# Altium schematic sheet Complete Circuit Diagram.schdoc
size 324 x 171 mm
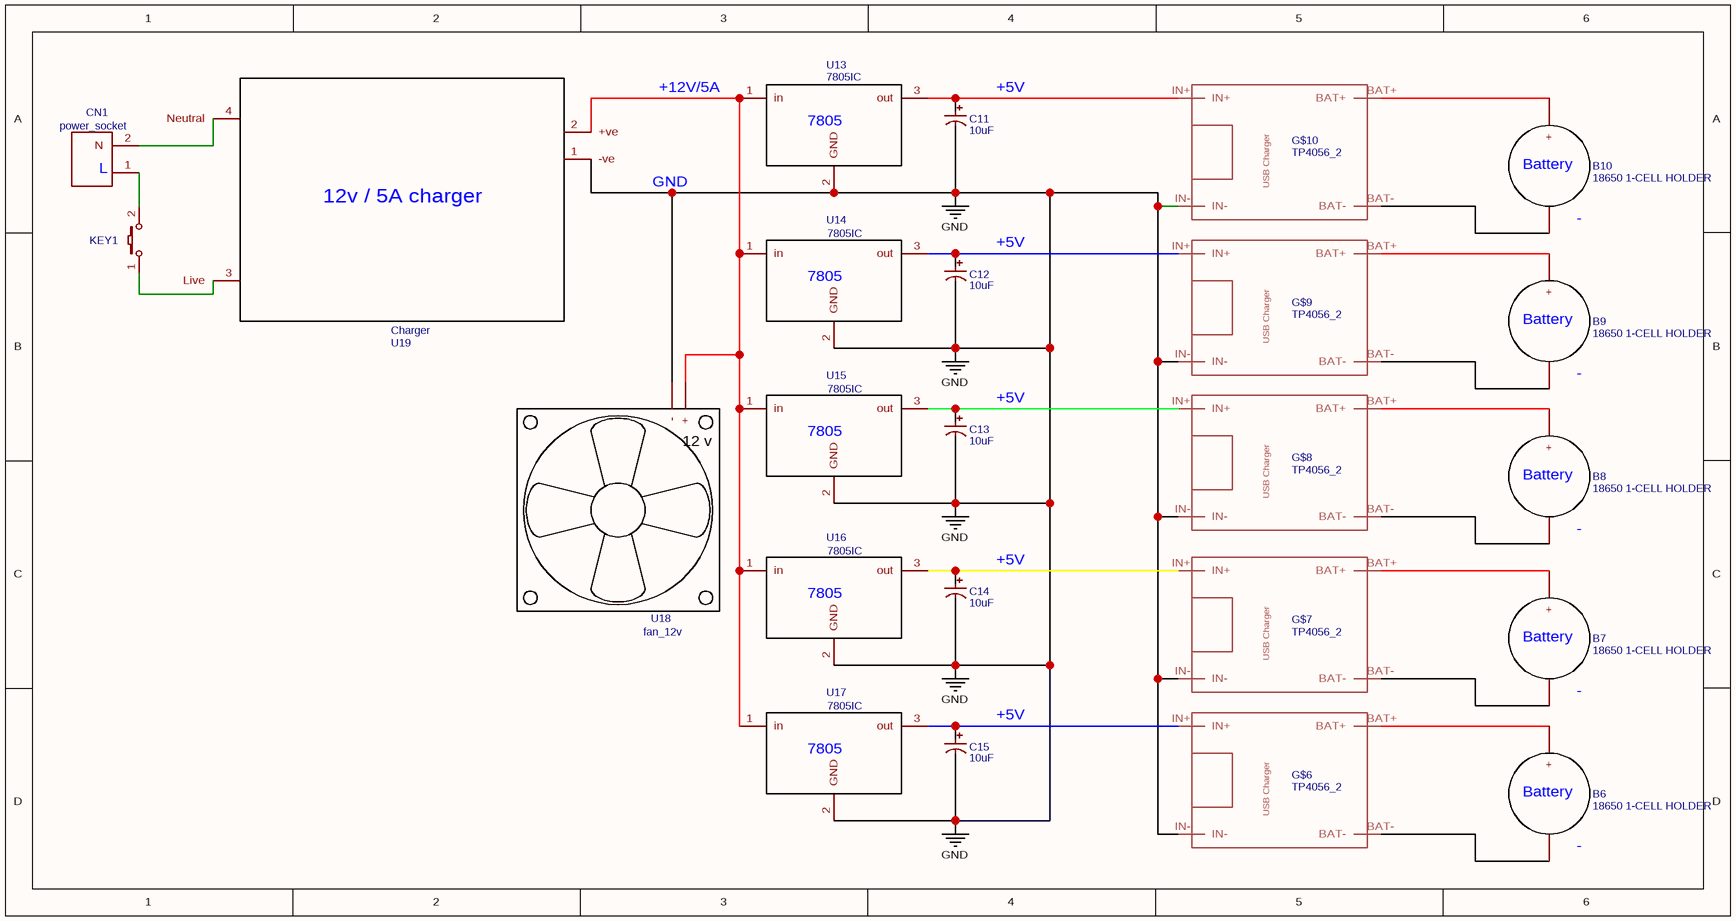
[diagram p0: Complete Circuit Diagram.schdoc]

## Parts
B6  18650 1-CELL HOLDER  [18650 1-CELL HOLDER]
B7  18650 1-CELL HOLDER  [18650 1-CELL HOLDER]
B8  18650 1-CELL HOLDER  [18650 1-CELL HOLDER]
B9  18650 1-CELL HOLDER  [18650 1-CELL HOLDER]
B10  18650 1-CELL HOLDER  [18650 1-CELL HOLDER]
C11  10uF  [CAPACITOR1000UF16V]
C12  10uF  [CAPACITOR1000UF16V]
C13  10uF  [CAPACITOR1000UF16V]
C14  10uF  [CAPACITOR1000UF16V]
C15  10uF  [CAPACITOR1000UF16V]
CN1  power_socket  [CONN-TH_SOCKET.BLUE5566-2ANEEDLE]
G$6  TP4056_2  [TP4056]
G$7  TP4056_2  [TP4056]
G$8  TP4056_2  [TP4056]
G$9  TP4056_2  [TP4056]
G$10  TP4056_2  [TP4056]
KEY1  K2-3.6×6.1_SMD  [KEY-SMD_2P-L6.2-W3.6-LS8.0]  (value not drawn)
U13  7805IC  [7805]
U14  7805IC  [7805]
U15  7805IC  [7805]
U16  7805IC  [7805]
U17  7805IC  [7805]
U18  fan_12v  [12V FAN]
U19  Charger  [CHARGER]

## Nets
GND: C11.2(-) C12.2(-) C13.2(-) C14.2(-) C15.2(-) G$6.IN- G$7.IN- G$8.IN- G$9.IN- G$10.IN- U13.2(GND) U14.2(GND) U15.2(GND) U16.2(GND) U17.2(GND) U18.2(-)
NetB6_1: B6.1(+) G$6.BAT+
NetB6_2: B6.2(-) G$6.BAT-
NetB7_1: B7.1(+) G$7.BAT+
NetB7_2: B7.2(-) G$7.BAT-
NetB8_1: B8.1(+) G$8.BAT+
NetB8_2: B8.2(-) G$8.BAT-
NetB9_1: B9.1(+) G$9.BAT+
NetB9_2: B9.2(-) G$9.BAT-
NetB10_1: B10.1(+) G$10.BAT+
NetB10_2: B10.2(-) G$10.BAT-
NetC11_1: C11.1(+) G$10.IN+ U13.3(out)
NetC12_1: C12.1(+) G$9.IN+ U14.3(out)
NetC13_1: C13.1(+) G$8.IN+ U15.3(out)
NetC14_1: C14.1(+) G$7.IN+ U16.3(out)
NetC15_1: C15.1(+) G$6.IN+ U17.3(out)
NetCN1_1: CN1.1(Line) KEY1.2
NetU13_1: U13.1(in) U14.1(in) U15.1(in) U16.1(in) U17.1(in) U18.1(+)

Not connected (* = marked no-connect by the designer): CN1 2(N); KEY1 1; U19 1(-ve) 2(+ve) 3(Live) 4(Neutral)

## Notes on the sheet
- +12V/5A
- (near C11) +5V
- (near CN1) L
- GND
- (near C12) +5V
- (near C13) +5V
- (near C14) +5V
- (near C15) +5V

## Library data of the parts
B6-B10 = 18650 1-CELL HOLDER: BOM_Manufacturer Part: Battery_holder_18650; Contributor: Visionz
C11-C15 = 10uF: BOM_Manufacturer: ValuePro; BOM_Manufacturer Part: electrolytic capacitor10UF50V; nameAlias: Capacitance
CN1 = power_socket: BOM_Manufacturer: BOOMELE; BOM_Manufacturer Part: socket.blue5566-2Aneedle; Contributor: F4IEY
G$6-G$10 = TP4056_2: Contributor: zillawilli
KEY1 = K2-3.6×6.1_SMD: BOM_Manufacturer Part: K2-1107ST-A4SW-06; Contributor: LCEDA_Lib; 制造商: 韩国韩荣
U13-U17 = 7805IC: Contributor: 53024
U18 = fan_12v: Contributor: ozgural
U19 = Charger: Contributor: bhaveshkale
